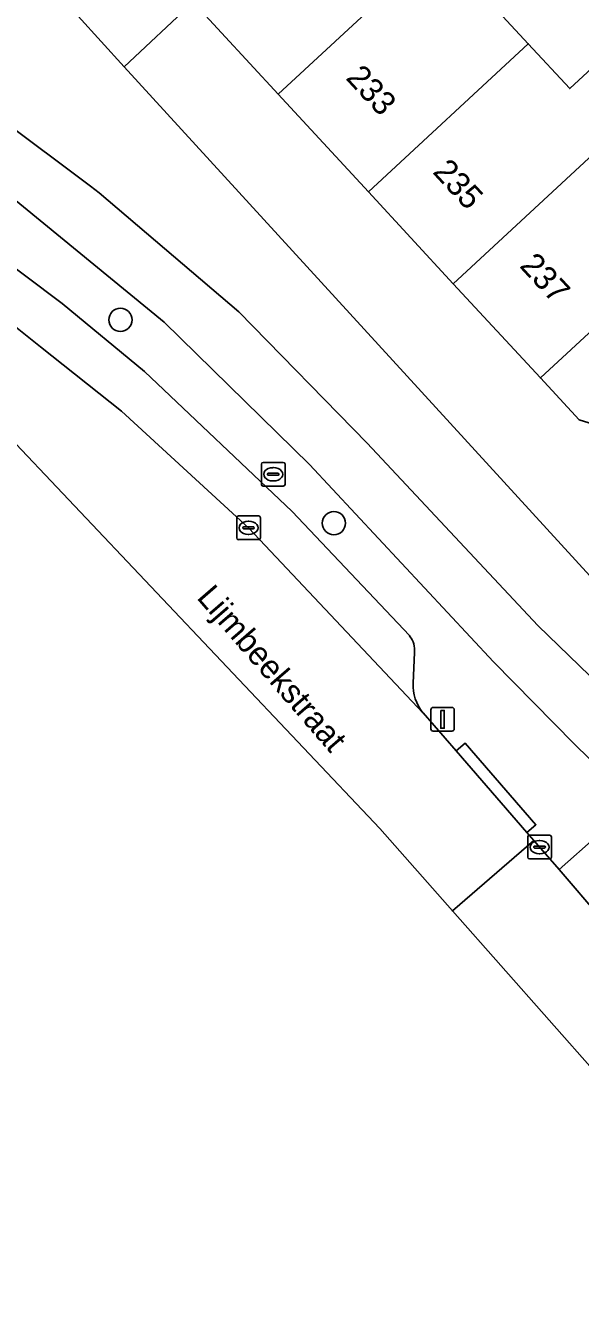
# Model space of a CAD drawing. Extents: x 159888 to 160761, y 384031 to 384750.
# Drawn here: x 160627.8 to 160651.2, y 384100.3 to 384154.2 of the extents above; entities that cross this region are included whole.
import ezdxf

# ---------------------------------------------------------------- set-up
doc = ezdxf.new("R2010")
doc.units = 0
for name, color, linetype in [('IMGEO_Berm_open', 7, 'Continuous'), ('IMGEO_Boom', 7, 'Continuous'), ('IMGEO_Erf', 7, 'Continuous'), ('IMGEO_Fietspad_open', 7, 'Continuous'), ('IMGEO_Kolk', 7, 'Continuous'), ('IMGEO_Lichtmast', 7, 'Continuous'), ('IMGEO_Openbare_ruimte_label', 7, 'Continuous'), ('IMGEO_Pand', 7, 'Continuous'), ('IMGEO_Pand_nummerreeks', 7, 'Continuous'), ('IMGEO_Parkeervlak_open', 7, 'Continuous'), ('IMGEO_Rijbaan_lokaal_gesloten', 7, 'Continuous'), ('IMGEO_Rijbaan_lokaal_open', 7, 'Continuous'), ('IMGEO_Rioolput', 7, 'Continuous'), ('IMGEO_Voetpad_open', 7, 'Continuous')]:
    doc.layers.add(name, color=color, linetype=linetype)

msp = doc.modelspace()

# ---------------------------------------------------------------- linework, layer by layer
at = {"layer": 'IMGEO_Berm_open'}
msp.add_lwpolyline([(160621.56, 384148.357), (160629.366, 384142.504), (160632.834, 384139.638), (160639.073, 384133.723), (160644.024, 384128.492), (160644.049, 384128.459), (160644.099, 384128.384), (160644.142, 384128.305), (160644.178, 384128.223), (160644.206, 384128.138), (160644.226, 384128.051), (160644.239, 384127.962), (160644.243, 384127.873), (160644.24, 384127.783), (160644.178, 384126.487), (160644.179, 384126.319), (160644.196, 384126.151), (160644.227, 384125.986), (160644.273, 384125.824), (160644.333, 384125.667), (160644.407, 384125.516), (160644.495, 384125.373), (160644.594, 384125.237), (160644.601, 384125.229), (160645.996, 384123.626), (160646.373, 384123.953), (160649.366, 384120.504), (160648.989, 384120.177), (160649.274, 384119.848), (160650.346, 384118.613), (160653.531, 384121.427), (160650.976, 384123.919), (160647.569, 384127.382), (160639.805, 384135.708), (160633.67, 384141.723), (160627.022, 384147.166)], dxfattribs=at)
at = {"layer": 'IMGEO_Boom'}
for centre in [(160631.825, 384141.818), (160640.837, 384133.237)]:
    msp.add_circle(centre, 0.489, dxfattribs=at)
at = {"layer": 'IMGEO_Erf'}
msp.add_lwpolyline([(160647.234, 384155.425), (160649.041, 384153.47), (160650.792, 384151.577), (160653.386, 384153.976)], dxfattribs=at)
msp.add_lwpolyline([(160642.291, 384147.225), (160638.481, 384151.345), (160634.89, 384155.229), (160631.987, 384152.495), (160651.648, 384131.01), (160654.195, 384135.039), (160653.692, 384135.26), (160653.756, 384135.43), (160651.971, 384137.36), (160651.188, 384137.603), (160649.558, 384139.366), (160645.879, 384143.345)], close=True, dxfattribs=at)
at = {"layer": 'IMGEO_Fietspad_open'}
for points in [[(160578.082, 384168.155), (160582.264, 384167.399), (160585.248, 384166.845), (160588.34, 384166.147), (160595.173, 384164.132), (160601.927, 384161.637), (160610.945, 384157.489), (160619.146, 384152.733), (160626.914, 384147.247), (160627.022, 384147.166), (160633.67, 384141.723), (160639.805, 384135.708), (160647.569, 384127.382), (160650.976, 384123.919), (160653.531, 384121.427), (160655.569, 384119.488)], [(160655.94, 384119.292), (160656.171, 384119.071), (160657.782, 384120.848), (160649.446, 384128.916), (160642.248, 384136.612), (160636.822, 384142.151), (160630.924, 384147.184), (160630.559, 384147.466), (160622.968, 384153.13), (160621.972, 384153.776)]]:
    msp.add_lwpolyline(points, dxfattribs=at)
at = {"layer": 'IMGEO_Kolk'}
for p, q in [((160636.733, 384132.614), (160636.733, 384133.466)), ((160636.808, 384133.54), (160637.66, 384133.54)), ((160637.221, 384133.32), (160637.246, 384133.32)), ((160637.734, 384133.466), (160637.734, 384132.614)), ((160636.992, 384133.034), (160636.992, 384133.046)), ((160637.43, 384132.997), (160637.032, 384132.997)), ((160637.035, 384133.083), (160637.433, 384133.083)), ((160637.244, 384132.76), (160637.219, 384132.76)), ((160637.476, 384133.046), (160637.476, 384133.034)), ((160637.66, 384132.54), (160636.808, 384132.54)), ((160649.021, 384119.138), (160649.021, 384119.99)), ((160649.096, 384120.064), (160649.948, 384120.064)), ((160649.509, 384119.844), (160649.534, 384119.844)), ((160650.022, 384119.99), (160650.022, 384119.138)), ((160649.28, 384119.558), (160649.28, 384119.57)), ((160649.718, 384119.521), (160649.32, 384119.521)), ((160649.323, 384119.607), (160649.721, 384119.607)), ((160649.532, 384119.284), (160649.507, 384119.284)), ((160649.764, 384119.57), (160649.764, 384119.558)), ((160649.948, 384119.064), (160649.096, 384119.064))]:
    msp.add_line(p, q, dxfattribs=at)
for points in [[(160636.733, 384132.614), (160636.733, 384133.466)], [(160636.808, 384133.54), (160637.66, 384133.54)], [(160637.734, 384133.466), (160637.734, 384132.614)], [(160637.66, 384132.54), (160636.808, 384132.54)], [(160649.021, 384119.138), (160649.021, 384119.99)], [(160649.096, 384120.064), (160649.948, 384120.064)], [(160650.022, 384119.99), (160650.022, 384119.138)], [(160649.948, 384119.064), (160649.096, 384119.064)]]:
    msp.add_lwpolyline(points, dxfattribs=at)
for centre, radius, start, end in [((160636.81, 384133.464), 0.0765, 91.552, 178.448), ((160636.81, 384133.464), 0.0765, 91.552, 178.448), ((160637.658, 384133.464), 0.0765, 1.552, 88.448), ((160637.658, 384133.464), 0.0765, 1.552, 88.448), ((160637.032, 384133.043), 0.0403, 85.8775, 175.7526), ((160637.029, 384133.033), 0.0366, 178.938, 274.7102), ((160637.433, 384133.04), 0.043, 264.8664, 352.4533), ((160637.437, 384133.045), 0.0386, 1.7309, 96.639), ((160636.81, 384132.616), 0.0765, 181.552, 268.448), ((160636.81, 384132.616), 0.0765, 181.552, 268.448), ((160637.658, 384132.616), 0.0765, 271.552, 358.448), ((160637.658, 384132.616), 0.0765, 271.552, 358.448), ((160649.098, 384119.988), 0.0765, 91.552, 178.448), ((160649.098, 384119.988), 0.0765, 91.552, 178.448), ((160649.946, 384119.988), 0.0765, 1.552, 88.448), ((160649.946, 384119.988), 0.0765, 1.552, 88.448), ((160649.32, 384119.567), 0.0403, 85.8775, 175.7526), ((160649.317, 384119.557), 0.0366, 178.938, 274.7102), ((160649.721, 384119.564), 0.043, 264.8664, 352.4533), ((160649.725, 384119.569), 0.0386, 1.7309, 96.639), ((160649.098, 384119.14), 0.0765, 181.552, 268.448), ((160649.098, 384119.14), 0.0765, 181.552, 268.448), ((160649.946, 384119.14), 0.0765, 271.552, 358.448), ((160649.946, 384119.14), 0.0765, 271.552, 358.448)]:
    msp.add_arc(centre, radius, start, end, dxfattribs=at)
for centre, major_axis, ratio, start_param, end_param in [((160637.22, 384133.04), (-0.387, 0.002), 0.722429, 4.712389, 7.853982), ((160637.245, 384133.04), (-0.39, 0.002), 0.717154, 1.570796, 4.712389), ((160649.508, 384119.564), (-0.387, 0.002), 0.722429, 4.712389, 7.853982), ((160649.533, 384119.564), (-0.39, 0.002), 0.717154, 1.570796, 4.712389)]:
    msp.add_ellipse(centre, major_axis=major_axis, ratio=ratio, start_param=start_param, end_param=end_param, dxfattribs=at)
at = {"layer": 'IMGEO_Lichtmast'}
for p, q in [((160644.929, 384124.558), (160644.929, 384125.358)), ((160644.929, 384125.358), (160644.929, 384124.558)), ((160645.029, 384125.458), (160645.819, 384125.458)), ((160645.819, 384125.458), (160645.029, 384125.458)), ((160645.919, 384125.358), (160645.919, 384124.558)), ((160645.919, 384124.558), (160645.919, 384125.358)), ((160645.819, 384124.458), (160645.029, 384124.458)), ((160645.029, 384124.458), (160645.819, 384124.458))]:
    msp.add_line(p, q, dxfattribs=at)
msp.add_lwpolyline([(160645.349, 384125.333), (160645.499, 384125.333), (160645.499, 384124.583), (160645.349, 384124.583), (160645.349, 384125.333)], dxfattribs=at)
for centre, start, end in [((160645.029, 384125.358), 90, 180), ((160645.029, 384125.358), 90, 180), ((160645.819, 384125.358), 0, 90), ((160645.819, 384125.358), 360, 90), ((160645.029, 384124.558), 180, 270), ((160645.029, 384124.558), 180, 270), ((160645.819, 384124.558), 270, 0), ((160645.819, 384124.558), 270, 0)]:
    msp.add_arc(centre, 0.1, start, end, dxfattribs=at)
at = {"layer": 'IMGEO_Pand'}
for points in [[(160647.927, 384160.083), (160646.414, 384161.719), (160646.065, 384162.097), (160644.334, 384163.969), (160641.707, 384161.538), (160641.354, 384161.212), (160638.139, 384158.235), (160637.911, 384158.025), (160634.89, 384155.229), (160638.481, 384151.345)], [(160641.354, 384161.212), (160641.16, 384161.422), (160640.753, 384161.862), (160639.795, 384162.898), (160638.684, 384162.375), (160636.578, 384160.501), (160634.917, 384162.298), (160635.235, 384162.592), (160634.81, 384163.052), (160631.744, 384160.217), (160628.097, 384156.795), (160631.987, 384152.495), (160634.89, 384155.229), (160637.911, 384158.025), (160638.139, 384158.235)], [(160642.291, 384147.225), (160649.041, 384153.47), (160647.234, 384155.425), (160649.929, 384157.918), (160647.927, 384160.083), (160638.481, 384151.345)], [(160655.222, 384151.99), (160653.386, 384153.976), (160650.792, 384151.577), (160649.041, 384153.47), (160642.291, 384147.225), (160645.879, 384143.345)], [(160655.222, 384151.99), (160645.879, 384143.345), (160649.558, 384139.366), (160656.21, 384145.521), (160654.393, 384147.486), (160657.085, 384149.975)], [(160659.462, 384142.003), (160656.21, 384145.521), (160649.558, 384139.366), (160651.188, 384137.603), (160651.971, 384137.36), (160653.756, 384135.43), (160653.692, 384135.26), (160654.195, 384135.039), (160654.205, 384135.035)]]:
    msp.add_lwpolyline(points, close=True, dxfattribs=at)
at = {"layer": 'IMGEO_Parkeervlak_open'}
msp.add_lwpolyline([(160622.096, 384145.751), (160628.452, 384140.673), (160631.864, 384137.964), (160637.241, 384133.031), (160644.594, 384125.237), (160644.495, 384125.373), (160644.407, 384125.516), (160644.333, 384125.667), (160644.273, 384125.824), (160644.227, 384125.986), (160644.196, 384126.151), (160644.179, 384126.319), (160644.178, 384126.487), (160644.24, 384127.783), (160644.243, 384127.873), (160644.239, 384127.962), (160644.226, 384128.051), (160644.206, 384128.138), (160644.178, 384128.223), (160644.142, 384128.305), (160644.099, 384128.384), (160644.049, 384128.459), (160644.024, 384128.492), (160639.073, 384133.723), (160632.834, 384139.638), (160629.366, 384142.504), (160621.56, 384148.357)], dxfattribs=at)
at = {"layer": 'IMGEO_Rijbaan_lokaal_gesloten'}
msp.add_lwpolyline([(160583.807, 384157.96), (160606.381, 384150.213), (160626.651, 384137.37), (160642.77, 384120.347), (160645.842, 384116.873), (160649.274, 384119.848), (160648.989, 384120.177), (160645.996, 384123.626), (160644.601, 384125.229), (160644.594, 384125.237), (160637.241, 384133.031), (160631.864, 384137.964), (160628.452, 384140.673), (160622.096, 384145.751), (160617.387, 384148.958), (160603.574, 384156.748)], dxfattribs=at)
at = {"layer": 'IMGEO_Rijbaan_lokaal_open'}
msp.add_lwpolyline([(160660.635, 384100.26), (160663.752, 384103.575), (160662.101, 384105.078), (160660.506, 384106.804), (160660.483, 384106.829), (160653.971, 384114.404), (160653.949, 384114.429), (160652.109, 384116.557), (160650.346, 384118.613), (160649.274, 384119.848), (160645.842, 384116.873), (160654, 384107.648), (160656.94, 384104.323)], close=True, dxfattribs=at)
at = {"layer": 'IMGEO_Rioolput'}
for p, q in [((160637.773, 384134.873), (160637.773, 384135.725)), ((160637.848, 384135.799), (160638.7, 384135.799)), ((160638.261, 384135.579), (160638.286, 384135.579)), ((160638.774, 384135.725), (160638.774, 384134.873)), ((160638.032, 384135.293), (160638.032, 384135.305)), ((160638.47, 384135.256), (160638.072, 384135.256)), ((160638.075, 384135.342), (160638.473, 384135.342)), ((160638.284, 384135.019), (160638.259, 384135.019)), ((160638.516, 384135.305), (160638.516, 384135.293)), ((160638.7, 384134.799), (160637.848, 384134.799))]:
    msp.add_line(p, q, dxfattribs=at)
for points in [[(160637.773, 384134.873), (160637.773, 384135.725)], [(160637.848, 384135.799), (160638.7, 384135.799)], [(160638.774, 384135.725), (160638.774, 384134.873)], [(160638.7, 384134.799), (160637.848, 384134.799)]]:
    msp.add_lwpolyline(points, dxfattribs=at)
for centre, radius, start, end in [((160637.85, 384135.723), 0.0765, 91.552, 178.448), ((160637.85, 384135.723), 0.0765, 91.552, 178.448), ((160638.698, 384135.723), 0.0765, 1.552, 88.448), ((160638.698, 384135.723), 0.0765, 1.552, 88.448), ((160637.85, 384134.875), 0.0765, 181.552, 268.448), ((160637.85, 384134.875), 0.0765, 181.552, 268.448), ((160638.072, 384135.302), 0.0403, 85.8775, 175.7526), ((160638.069, 384135.292), 0.0366, 178.938, 274.7102), ((160638.473, 384135.299), 0.043, 264.8664, 352.4533), ((160638.477, 384135.304), 0.0386, 1.7309, 96.639), ((160638.698, 384134.875), 0.0765, 271.552, 358.448), ((160638.698, 384134.875), 0.0765, 271.552, 358.448)]:
    msp.add_arc(centre, radius, start, end, dxfattribs=at)
for centre, major_axis, ratio, start_param, end_param in [((160638.26, 384135.299), (-0.387, 0.002), 0.722429, 4.712389, 7.853982), ((160638.285, 384135.299), (-0.39, 0.002), 0.717154, 1.570796, 4.712389)]:
    msp.add_ellipse(centre, major_axis=major_axis, ratio=ratio, start_param=start_param, end_param=end_param, dxfattribs=at)
at = {"layer": 'IMGEO_Voetpad_open'}
for points in [[(160631.987, 384152.495), (160628.097, 384156.795)], [(160622.968, 384153.13), (160630.559, 384147.466), (160630.924, 384147.184), (160636.822, 384142.151), (160642.248, 384136.612), (160649.446, 384128.916), (160657.782, 384120.848)], [(160651.648, 384131.01), (160631.987, 384152.495)]]:
    msp.add_lwpolyline(points, dxfattribs=at)
for points in [[(160648.989, 384120.177), (160649.366, 384120.504), (160646.373, 384123.953), (160645.996, 384123.626)], [(160650.346, 384118.613), (160652.109, 384116.557), (160655.229, 384119.319), (160655.569, 384119.488), (160653.531, 384121.427)]]:
    msp.add_lwpolyline(points, close=True, dxfattribs=at)

# ---------------------------------------------------------------- texts
at = {"layer": 'IMGEO_Openbare_ruimte_label'}
msp.add_text('Lijmbeekstraat', height=1, rotation=310.8624, dxfattribs=at).set_placement((160635.01, 384130.08))
at = {"layer": 'IMGEO_Pand_nummerreeks'}
for s, p in [('233', (160641.304, 384152.003)), ('235', (160644.972, 384148.037)), ('237', (160648.639, 384144.072))]:
    msp.add_text(s, height=1, rotation=312.7584, dxfattribs=at).set_placement(p)

doc.saveas('drawing.dxf')
